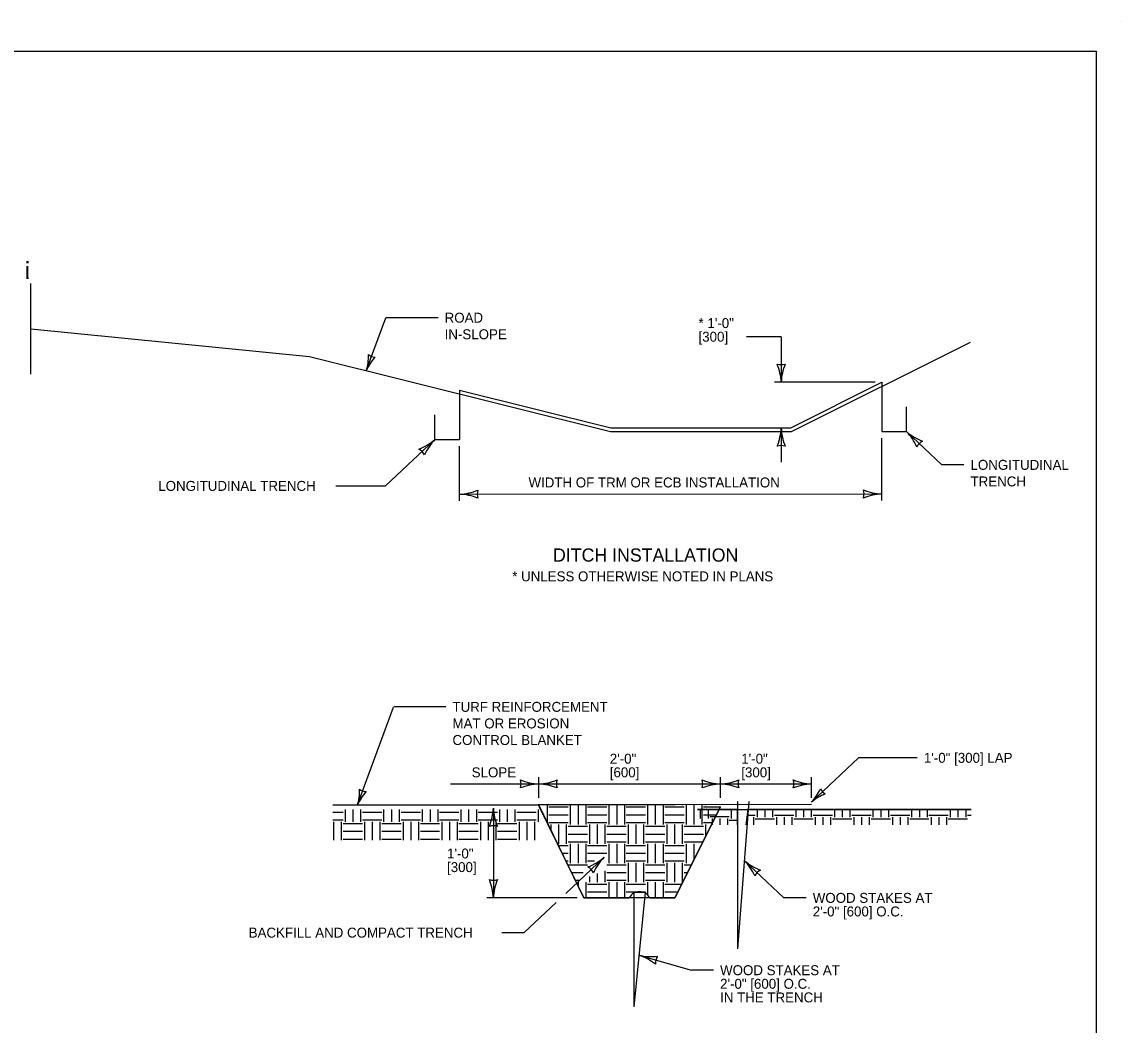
# Model space of a CAD drawing. Extents: x 49977.1 to 50021, y 49987.6 to 50011.4.
# Drawn here: x 50010.27 to 50016.9, y 49993.13 to 49999.18 of the extents above; entities that cross this region are included whole.
import ezdxf

# ---------------------------------------------------------------- set-up
doc = ezdxf.new("R2010")
doc.units = 0
for name, color, linetype in [('Level 1', 7, 'Continuous'), ('Level 2', 7, 'Continuous'), ('Level 3', 7, 'Continuous'), ('Level 5', 7, 'Continuous'), ('Level 60', 7, 'Continuous')]:
    doc.layers.add(name, color=color, linetype=linetype)

msp = doc.modelspace()

# ---------------------------------------------------------------- linework, layer by layer
at = {"layer": 'Level 1'}
for p, q in [((50016.9001, 49999.1756), (50016.9001, 49999.1756)), ((50010.3258, 49997.3257), (50012.0064, 49997.158)), ((50014.9133, 49996.7055), (50015.9917, 49997.2455)), ((50012.0064, 49997.158), (50013.8211, 49996.7055)), ((50014.9082, 49996.7274), (50015.4574, 49997.0024)), ((50015.4574, 49997.0024), (50015.4574, 49996.7055)), ((50012.9111, 49996.9549), (50013.8237, 49996.7274)), ((50012.9111, 49996.9549), (50012.9111, 49996.658)), ((50012.7626, 49996.658), (50012.7626, 49996.8065)), ((50015.6059, 49996.7055), (50015.6059, 49996.854)), ((50013.8237, 49996.7274), (50014.9082, 49996.7274)), ((50012.7626, 49996.658), (50012.9111, 49996.658)), ((50013.8211, 49996.7055), (50014.9133, 49996.7055)), ((50015.4574, 49996.7055), (50015.6059, 49996.7055)), ((50014.6556, 49994.474), (50014.5869, 49993.5859)), ((50014.5869, 49994.474), (50014.5869, 49993.5859)), ((50012.1463, 49994.4539), (50013.3822, 49994.4539)), ((50012.1463, 49994.4105), (50012.2084, 49994.4105)), ((50012.2201, 49994.4257), (50012.2201, 49994.3523)), ((50012.2667, 49994.4257), (50012.2667, 49994.3523)), ((50012.3133, 49994.4257), (50012.3133, 49994.3523)), ((50012.3249, 49994.4105), (50012.4414, 49994.4105)), ((50012.4531, 49994.4257), (50012.4531, 49994.3523)), ((50012.4997, 49994.4257), (50012.4997, 49994.3523)), ((50012.5463, 49994.4257), (50012.5463, 49994.3523)), ((50012.5579, 49994.4105), (50012.6744, 49994.4105)), ((50012.6861, 49994.4257), (50012.6861, 49994.3523)), ((50012.7327, 49994.4257), (50012.7327, 49994.3523)), ((50012.7792, 49994.4257), (50012.7792, 49994.3523)), ((50012.7909, 49994.4105), (50012.9074, 49994.4105)), ((50012.919, 49994.4257), (50012.919, 49994.3523)), ((50012.9656, 49994.4257), (50012.9656, 49994.3523)), ((50013.0122, 49994.4257), (50013.0122, 49994.3523)), ((50013.0239, 49994.4105), (50013.1404, 49994.4105)), ((50013.152, 49994.4257), (50013.152, 49994.3523)), ((50013.1986, 49994.4257), (50013.1986, 49994.3523)), ((50013.2452, 49994.4257), (50013.2452, 49994.3523)), ((50013.2569, 49994.4105), (50013.3734, 49994.4105)), ((50013.385, 49994.4257), (50013.385, 49994.3523)), ((50013.4391, 49994.4522), (50013.4391, 49994.3437)), ((50013.4499, 49994.4414), (50013.5664, 49994.4414)), ((50013.4615, 49994.4541), (50013.4615, 49994.4522)), ((50013.5081, 49994.4542), (50013.5081, 49994.4522)), ((50013.5547, 49994.4543), (50013.5547, 49994.4522)), ((50013.5789, 49994.4522), (50013.5789, 49994.3357)), ((50013.6255, 49994.4522), (50013.6255, 49994.3357)), ((50013.6721, 49994.4522), (50013.6721, 49994.3357)), ((50013.6829, 49994.4414), (50013.7994, 49994.4414)), ((50013.6945, 49994.4547), (50013.6945, 49994.4522)), ((50013.7411, 49994.4548), (50013.7411, 49994.4522)), ((50013.7877, 49994.4549), (50013.7877, 49994.4522)), ((50013.8119, 49994.4522), (50013.8119, 49994.3357)), ((50013.8585, 49994.4522), (50013.8585, 49994.3357)), ((50013.9051, 49994.4522), (50013.9051, 49994.3357)), ((50013.9159, 49994.4414), (50014.0324, 49994.4414)), ((50013.9275, 49994.4553), (50013.9275, 49994.4522)), ((50013.9741, 49994.4554), (50013.9741, 49994.4522)), ((50014.0207, 49994.4556), (50014.0207, 49994.4522)), ((50014.0449, 49994.4522), (50014.0449, 49994.3357)), ((50014.0915, 49994.4522), (50014.0915, 49994.3357)), ((50014.1381, 49994.4522), (50014.1381, 49994.3357)), ((50014.1488, 49994.4414), (50014.2653, 49994.4414)), ((50014.1605, 49994.4559), (50014.1605, 49994.4522)), ((50014.2071, 49994.456), (50014.2071, 49994.4522)), ((50014.2537, 49994.4562), (50014.2537, 49994.4522)), ((50014.2779, 49994.4522), (50014.2779, 49994.3357)), ((50014.3245, 49994.4522), (50014.3245, 49994.3357)), ((50014.3463, 49994.4257), (50015.9963, 49994.4257)), ((50014.5869, 49994.4257), (50014.3463, 49994.4257)), ((50014.3627, 49994.4257), (50014.3627, 49994.3726)), ((50014.3711, 49994.4522), (50014.3711, 49994.3357)), ((50014.3818, 49994.4414), (50014.4842, 49994.4414)), ((50014.3935, 49994.4565), (50014.3935, 49994.4522)), ((50014.4093, 49994.4257), (50014.4093, 49994.3726)), ((50014.5491, 49994.4257), (50014.5491, 49994.3726)), ((50014.5869, 49994.334), (50014.5869, 49994.4257)), ((50014.6496, 49994.4257), (50014.6381, 49994.334)), ((50015.9963, 49994.4257), (50014.6496, 49994.4257)), ((50014.7052, 49994.4257), (50014.7052, 49994.3799)), ((50014.7518, 49994.4257), (50014.7518, 49994.3799)), ((50014.7984, 49994.4257), (50014.7984, 49994.3799)), ((50014.9382, 49994.4257), (50014.9382, 49994.3799)), ((50014.9848, 49994.4257), (50014.9848, 49994.3799)), ((50015.0314, 49994.4257), (50015.0314, 49994.3799)), ((50015.1712, 49994.4257), (50015.1712, 49994.3799)), ((50015.2178, 49994.4257), (50015.2178, 49994.3799)), ((50015.2644, 49994.4257), (50015.2644, 49994.3799)), ((50015.4042, 49994.4257), (50015.4042, 49994.3799)), ((50015.4508, 49994.4257), (50015.4508, 49994.3799)), ((50015.4974, 49994.4257), (50015.4974, 49994.3799)), ((50015.6372, 49994.4257), (50015.6372, 49994.3799)), ((50015.6838, 49994.4257), (50015.6838, 49994.3799)), ((50015.7304, 49994.4257), (50015.7304, 49994.3799)), ((50015.8702, 49994.4257), (50015.8702, 49994.3799)), ((50015.9168, 49994.4257), (50015.9168, 49994.3799)), ((50015.9634, 49994.4257), (50015.9634, 49994.3799)), ((50012.1463, 49994.3639), (50012.2084, 49994.3639)), ((50012.151, 49994.3523), (50012.151, 49994.2423)), ((50012.1976, 49994.3523), (50012.1976, 49994.2423)), ((50012.2084, 49994.3415), (50012.3249, 49994.3415)), ((50012.3249, 49994.3639), (50012.4414, 49994.3639)), ((50012.3374, 49994.3523), (50012.3374, 49994.2423)), ((50012.384, 49994.3523), (50012.384, 49994.2423)), ((50012.4306, 49994.3523), (50012.4306, 49994.2423)), ((50012.4414, 49994.3415), (50012.5579, 49994.3415)), ((50012.5579, 49994.3639), (50012.6744, 49994.3639)), ((50012.5704, 49994.3523), (50012.5704, 49994.2423)), ((50012.617, 49994.3523), (50012.617, 49994.2423)), ((50012.6636, 49994.3523), (50012.6636, 49994.2423)), ((50012.6744, 49994.3415), (50012.7909, 49994.3415)), ((50012.7909, 49994.3639), (50012.9074, 49994.3639)), ((50012.8034, 49994.3523), (50012.8034, 49994.2423)), ((50012.85, 49994.3523), (50012.85, 49994.2423)), ((50012.8966, 49994.3523), (50012.8966, 49994.2423)), ((50012.9074, 49994.3415), (50013.0239, 49994.3415)), ((50013.0239, 49994.3639), (50013.1404, 49994.3639)), ((50013.0364, 49994.3523), (50013.0364, 49994.2423)), ((50013.083, 49994.3523), (50013.083, 49994.2423)), ((50013.1296, 49994.3523), (50013.1296, 49994.2423)), ((50013.1404, 49994.3415), (50013.2569, 49994.3415)), ((50013.2569, 49994.3639), (50013.3734, 49994.3639)), ((50013.2694, 49994.3523), (50013.2694, 49994.2423)), ((50013.316, 49994.3523), (50013.316, 49994.2423)), ((50013.3626, 49994.3523), (50013.3626, 49994.2423)), ((50013.4499, 49994.3948), (50013.5664, 49994.3948)), ((50013.4499, 49994.3482), (50013.5664, 49994.3482)), ((50013.6829, 49994.3948), (50013.7994, 49994.3948)), ((50013.6829, 49994.3482), (50013.7994, 49994.3482)), ((50013.9159, 49994.3948), (50014.0324, 49994.3948)), ((50013.9159, 49994.3482), (50014.0324, 49994.3482)), ((50014.1488, 49994.3948), (50014.2653, 49994.3948)), ((50014.1488, 49994.3482), (50014.2653, 49994.3482)), ((50014.3818, 49994.3948), (50014.4609, 49994.3948)), ((50014.3818, 49994.3482), (50014.4376, 49994.3482)), ((50014.4209, 49994.3842), (50014.5374, 49994.3842)), ((50014.4334, 49994.3726), (50014.4334, 49994.334)), ((50014.48, 49994.3726), (50014.48, 49994.334)), ((50014.5266, 49994.3726), (50014.5266, 49994.334)), ((50014.5374, 49994.3618), (50014.5869, 49994.3618)), ((50014.6453, 49994.3916), (50014.6936, 49994.3916)), ((50014.6828, 49994.3799), (50014.6828, 49994.334)), ((50014.6936, 49994.3691), (50014.8101, 49994.3691)), ((50014.8101, 49994.3916), (50014.9266, 49994.3916)), ((50014.8226, 49994.3799), (50014.8226, 49994.334)), ((50014.8692, 49994.3799), (50014.8692, 49994.334)), ((50014.9158, 49994.3799), (50014.9158, 49994.334)), ((50014.9266, 49994.3691), (50015.0431, 49994.3691)), ((50015.0431, 49994.3916), (50015.1596, 49994.3916)), ((50015.0556, 49994.3799), (50015.0556, 49994.334)), ((50015.1022, 49994.3799), (50015.1022, 49994.334)), ((50015.1488, 49994.3799), (50015.1488, 49994.334)), ((50015.1596, 49994.3691), (50015.2761, 49994.3691)), ((50015.2761, 49994.3916), (50015.3926, 49994.3916)), ((50015.2886, 49994.3799), (50015.2886, 49994.334)), ((50015.3352, 49994.3799), (50015.3352, 49994.334)), ((50015.3818, 49994.3799), (50015.3818, 49994.334)), ((50015.3926, 49994.3691), (50015.509, 49994.3691)), ((50015.509, 49994.3916), (50015.6255, 49994.3916)), ((50015.5216, 49994.3799), (50015.5216, 49994.334)), ((50015.5682, 49994.3799), (50015.5682, 49994.334)), ((50015.6148, 49994.3799), (50015.6148, 49994.334)), ((50015.6255, 49994.3691), (50015.742, 49994.3691)), ((50015.742, 49994.3916), (50015.8585, 49994.3916)), ((50015.7546, 49994.3799), (50015.7546, 49994.334)), ((50015.8012, 49994.3799), (50015.8012, 49994.334)), ((50015.8478, 49994.3799), (50015.8478, 49994.334)), ((50015.8585, 49994.3691), (50015.975, 49994.3691)), ((50015.975, 49994.3916), (50015.9963, 49994.3916)), ((50012.2084, 49994.2949), (50012.3249, 49994.2949)), ((50012.4414, 49994.2949), (50012.5579, 49994.2949)), ((50012.6744, 49994.2949), (50012.7909, 49994.2949)), ((50012.9074, 49994.2949), (50013.0239, 49994.2949)), ((50013.1404, 49994.2949), (50013.2569, 49994.2949)), ((50013.4483, 49994.3249), (50013.4499, 49994.3249)), ((50013.4615, 49994.3365), (50013.4615, 49994.298)), ((50013.5081, 49994.3365), (50013.5081, 49994.22)), ((50013.5547, 49994.3365), (50013.5547, 49994.22)), ((50013.5664, 49994.3249), (50013.6829, 49994.3249)), ((50013.5664, 49994.2783), (50013.6829, 49994.2783)), ((50013.6945, 49994.3365), (50013.6945, 49994.22)), ((50013.7411, 49994.3365), (50013.7411, 49994.22)), ((50013.7877, 49994.3365), (50013.7877, 49994.22)), ((50013.7994, 49994.3249), (50013.9159, 49994.3249)), ((50013.7994, 49994.2783), (50013.9159, 49994.2783)), ((50013.9275, 49994.3365), (50013.9275, 49994.22)), ((50013.9741, 49994.3365), (50013.9741, 49994.22)), ((50014.0207, 49994.3365), (50014.0207, 49994.22)), ((50014.0324, 49994.3249), (50014.1488, 49994.3249)), ((50014.0324, 49994.2783), (50014.1488, 49994.2783)), ((50014.1605, 49994.3365), (50014.1605, 49994.22)), ((50014.2071, 49994.3365), (50014.2071, 49994.22)), ((50014.2537, 49994.3365), (50014.2537, 49994.22)), ((50014.2653, 49994.3249), (50014.3818, 49994.3249)), ((50014.2653, 49994.2783), (50014.3818, 49994.2783)), ((50014.3935, 49994.3365), (50014.3935, 49994.26)), ((50012.2084, 49994.2483), (50012.3249, 49994.2483)), ((50012.4414, 49994.2483), (50012.5579, 49994.2483)), ((50012.6744, 49994.2483), (50012.7909, 49994.2483)), ((50012.9074, 49994.2483), (50013.0239, 49994.2483)), ((50013.1404, 49994.2483), (50013.2569, 49994.2483)), ((50013.5051, 49994.2092), (50013.5664, 49994.2092)), ((50013.5664, 49994.2317), (50013.6829, 49994.2317)), ((50013.5789, 49994.22), (50013.5789, 49994.1035)), ((50013.6255, 49994.22), (50013.6255, 49994.1035)), ((50013.6721, 49994.22), (50013.6721, 49994.1035)), ((50013.6829, 49994.2092), (50013.7994, 49994.2092)), ((50013.7994, 49994.2317), (50013.9159, 49994.2317)), ((50013.8119, 49994.22), (50013.8119, 49994.1035)), ((50013.8585, 49994.22), (50013.8585, 49994.1035)), ((50013.9051, 49994.22), (50013.9051, 49994.1035)), ((50013.9159, 49994.2092), (50014.0324, 49994.2092)), ((50014.0324, 49994.2317), (50014.1488, 49994.2317)), ((50014.0449, 49994.22), (50014.0449, 49994.1035)), ((50014.0915, 49994.22), (50014.0915, 49994.1035)), ((50014.1381, 49994.22), (50014.1381, 49994.1035)), ((50014.1488, 49994.2092), (50014.2653, 49994.2092)), ((50014.2653, 49994.2317), (50014.3793, 49994.2317)), ((50014.2779, 49994.22), (50014.2779, 49994.1035)), ((50014.3245, 49994.22), (50014.3245, 49994.1219)), ((50014.3711, 49994.22), (50014.3711, 49994.2151)), ((50013.528, 49994.1626), (50013.5664, 49994.1626)), ((50013.6829, 49994.1626), (50013.7994, 49994.1626)), ((50013.9159, 49994.1626), (50014.0324, 49994.1626)), ((50014.1488, 49994.1626), (50014.2653, 49994.1626)), ((50013.5508, 49994.116), (50013.5664, 49994.116)), ((50013.5664, 49994.0927), (50013.6829, 49994.0927)), ((50013.6829, 49994.116), (50013.7244, 49994.116)), ((50013.7994, 49994.0927), (50013.9159, 49994.0927)), ((50013.9159, 49994.116), (50014.0324, 49994.116)), ((50013.9275, 49994.1044), (50013.9275, 49993.9879)), ((50013.9741, 49994.1044), (50013.9741, 49993.9879)), ((50014.0207, 49994.1044), (50014.0207, 49993.9879)), ((50014.0324, 49994.0927), (50014.1488, 49994.0927)), ((50014.1488, 49994.116), (50014.2653, 49994.116)), ((50014.1605, 49994.1044), (50014.1605, 49993.9879)), ((50014.2071, 49994.1044), (50014.2071, 49993.9879)), ((50014.2537, 49994.1044), (50014.2537, 49993.9879)), ((50014.2653, 49994.0927), (50014.3098, 49994.0927)), ((50013.5851, 49994.0461), (50013.6562, 49994.0461)), ((50013.6945, 49994.0225), (50013.6945, 49993.9879)), ((50013.7411, 49994.0405), (50013.7411, 49993.9879)), ((50013.7877, 49994.0573), (50013.7877, 49993.9879)), ((50013.7994, 49994.0461), (50013.9159, 49994.0461)), ((50014.0324, 49994.0461), (50014.1488, 49994.0461)), ((50014.2653, 49994.0461), (50014.2866, 49994.0461)), ((50013.608, 49993.9995), (50013.6343, 49993.9995)), ((50013.6255, 49993.9879), (50013.6255, 49993.9639)), ((50013.6721, 49993.9879), (50013.6721, 49993.8933)), ((50013.6829, 49993.977), (50013.7994, 49993.977)), ((50013.7994, 49993.9995), (50013.9159, 49993.9995)), ((50013.8119, 49993.9879), (50013.8119, 49993.8933)), ((50013.8585, 49993.9879), (50013.8585, 49993.8933)), ((50013.9051, 49993.9879), (50013.9051, 49993.8933)), ((50013.9159, 49993.977), (50014.0324, 49993.977)), ((50014.0324, 49993.9995), (50014.1488, 49993.9995)), ((50014.0449, 49993.9879), (50014.0449, 49993.9109)), ((50014.0915, 49993.9879), (50014.0915, 49993.8933)), ((50014.1381, 49993.9879), (50014.1381, 49993.8933)), ((50014.1488, 49993.977), (50014.252, 49993.977)), ((50013.6829, 49993.9304), (50013.7994, 49993.9304)), ((50013.9159, 49993.9304), (50013.9863, 49993.9304)), ((50013.9615, 49993.9285), (50013.9615, 49993.2356)), ((50014.0303, 49993.9285), (50013.9615, 49993.2356)), ((50013.9615, 49993.9285), (50014.0303, 49993.9285)), ((50014.0056, 49993.9304), (50014.0324, 49993.9304)), ((50014.1488, 49993.9304), (50014.2287, 49993.9304))]:
    msp.add_line(p, q, dxfattribs=at)
msp.add_lwpolyline([(49999.3835, 49998.9992), (50016.7501, 49998.9992), (50016.7501, 49987.7988), (49999.3835, 49987.7988)], close=True, dxfattribs=at)
for points in [[(50014.4996, 49994.4568), (50013.385, 49994.4539)], [(50013.385, 49994.4539), (50013.3902, 49994.4433), (50013.6601, 49993.8933), (50013.9341, 49993.8933)], [(50014.0578, 49993.8933), (50014.2101, 49993.8933), (50014.4393, 49994.3516), (50014.4851, 49994.4433)]]:
    msp.add_lwpolyline(points, dxfattribs=at)
msp.add_arc((50013.9959, 49993.8616), 0.0695, 27.10314, 152.89686, dxfattribs=at)
at = {"layer": 'Level 3'}
for p, q in [((50012.3482, 49997.0727), (50012.4662, 49997.3913)), ((50012.7809, 49997.3923), (50012.4665, 49997.3923)), ((50014.8506, 49997.2775), (50014.6413, 49997.2775)), ((50014.8506, 49997.2775), (50014.8506, 49997.0024)), ((50015.4174, 49997.0024), (50014.8106, 49997.0024)), ((50014.8506, 49996.7274), (50014.8506, 49996.5209)), ((50012.7626, 49996.658), (50012.4652, 49996.3778)), ((50015.4574, 49996.2892), (50015.4574, 49996.6655)), ((50015.6059, 49996.7055), (50015.8191, 49996.5047)), ((50012.9111, 49996.2878), (50012.9111, 49996.618)), ((50015.9525, 49996.5047), (50015.8191, 49996.5047)), ((50012.1647, 49996.3778), (50012.4652, 49996.3778)), ((50012.9111, 49996.3278), (50015.4574, 49996.3292)), ((50012.2948, 49994.4539), (50012.5134, 49995.0443)), ((50012.8282, 49995.0453), (50012.5138, 49995.0453)), ((50015.0342, 49994.4715), (50015.317, 49994.7379)), ((50015.6714, 49994.7379), (50015.317, 49994.7379)), ((50013.3887, 49994.4968), (50013.3887, 49994.6204)), ((50014.4842, 49994.4968), (50014.4842, 49994.6204)), ((50015.0342, 49994.4968), (50015.0342, 49994.6204)), ((50012.8572, 49994.5804), (50013.3887, 49994.5804)), ((50013.3887, 49994.5804), (50014.4842, 49994.5804)), ((50014.4842, 49994.5804), (50015.0342, 49994.5804)), ((50013.1149, 49994.4349), (50013.1149, 49993.8933)), ((50013.7824, 49994.1381), (50013.5517, 49993.9207)), ((50014.6281, 49994.1189), (50014.8675, 49993.8933)), ((50013.6201, 49993.8933), (50013.0749, 49993.8933)), ((50015.001, 49993.8933), (50014.8675, 49993.8933)), ((50013.4935, 49993.8658), (50013.3001, 49993.6837)), ((50013.1667, 49993.6837), (50013.3001, 49993.6837)), ((50013.9925, 49993.5478), (50014.3087, 49993.4571)), ((50014.4421, 49993.4571), (50014.3087, 49993.4571))]:
    msp.add_line(p, q, dxfattribs=at)
for centre, radius, start, end in [((50012.0828, 49997.1588), 0.279, 342.04462, 2.22813), ((50012.6171, 49996.9578), 0.2924, 137.60698, 156.85683), ((50012.4041, 49997.2236), 0.0687, 231.82296, 267.54532), ((50014.8506, 49997.1884), 0.0794, 252.13882, 287.86118), ((50014.5131, 49996.9857), 0.3379, 2.82731, 22.07716), ((50015.1728, 49996.9891), 0.3224, 157.45601, 177.63952), ((50014.5285, 49996.7406), 0.3224, 337.45601, 357.63952), ((50015.1881, 49996.744), 0.3379, 182.82731, 202.07716), ((50012.5433, 49996.9151), 0.3379, 291.21884, 310.46869), ((50012.9932, 49996.4327), 0.3224, 135.65648, 155.83999), ((50015.3753, 49996.4802), 0.3224, 24.16001, 44.34352), ((50015.8252, 49996.9626), 0.3379, 229.53131, 248.78116), ((50012.6273, 49996.5305), 0.0794, 25.43482, 61.15718), ((50014.8506, 49996.5414), 0.0794, 72.13882, 107.86118), ((50015.7412, 49996.578), 0.0794, 118.84282, 154.56518), ((50012.8944, 49996.6653), 0.3379, 272.82731, 292.07716), ((50012.8978, 49996.0057), 0.3224, 67.45601, 87.63952), ((50013.097, 49996.3278), 0.0794, 162.13882, 197.86118), ((50015.4707, 49996.6514), 0.3224, 247.45601, 267.63952), ((50015.2715, 49996.3292), 0.0794, 342.13882, 17.86118), ((50015.4741, 49995.9917), 0.3379, 92.82731, 112.07716), ((50013.402, 49994.9025), 0.3224, 247.45601, 267.63952), ((50013.2027, 49994.5804), 0.0794, 342.13882, 17.86118), ((50013.372, 49994.9179), 0.3379, 272.82731, 292.07716), ((50013.5746, 49994.5804), 0.0794, 162.13882, 197.86118), ((50014.4975, 49994.9025), 0.3224, 247.45601, 267.63952), ((50014.2982, 49994.5804), 0.0794, 342.13882, 17.86118), ((50014.4675, 49994.9179), 0.3379, 272.82731, 292.07716), ((50014.6701, 49994.5804), 0.0794, 162.13882, 197.86118), ((50015.0475, 49994.9025), 0.3224, 247.45601, 267.63952), ((50014.8482, 49994.5804), 0.0794, 342.13882, 17.86118), ((50012.0287, 49994.5376), 0.279, 342.04462, 2.22813), ((50012.35, 49994.6025), 0.0687, 231.82296, 267.54532), ((50013.4054, 49994.2429), 0.3379, 92.82731, 112.07716), ((50013.3754, 49994.2582), 0.3224, 67.45601, 87.63952), ((50014.5009, 49994.2429), 0.3379, 92.82731, 112.07716), ((50014.4709, 49994.2582), 0.3224, 67.45601, 87.63952), ((50015.0509, 49994.2429), 0.3379, 92.82731, 112.07716), ((50014.833, 49994.6648), 0.279, 315.65648, 335.83999), ((50015.1496, 49994.5801), 0.0687, 205.43482, 241.15718), ((50012.563, 49994.3367), 0.2924, 137.60698, 156.85683), ((50015.2223, 49994.2473), 0.2924, 111.21884, 130.46869), ((50012.7927, 49994.4482), 0.3224, 337.45601, 357.63952), ((50013.4524, 49994.4516), 0.3379, 182.82731, 202.07716), ((50013.1149, 49994.249), 0.0794, 72.13882, 107.86118), ((50013.5631, 49994.3951), 0.3379, 291.21884, 310.46869), ((50014.013, 49993.9127), 0.3224, 135.65648, 155.83999), ((50013.647, 49994.0105), 0.0794, 25.43482, 61.15718), ((50014.3975, 49993.8935), 0.3224, 24.16001, 44.34352), ((50014.8475, 49994.376), 0.3379, 229.53131, 248.78116), ((50014.7635, 49993.9914), 0.0794, 118.84282, 154.56518), ((50013.1149, 49994.0792), 0.0794, 252.13882, 287.86118), ((50012.7774, 49993.8766), 0.3379, 2.82731, 22.07716), ((50013.437, 49993.88), 0.3224, 157.45601, 177.63952), ((50013.8909, 49993.2417), 0.3224, 51.45141, 71.63492), ((50014.0695, 49993.8768), 0.3379, 256.82271, 276.07256), ((50014.1712, 49993.4965), 0.0794, 146.13422, 181.85658)]:
    msp.add_arc(centre, radius, start, end, dxfattribs=at)
at = {"layer": 'Level 5'}
msp.add_line((50010.3258, 49997.0526), (50010.3258, 49997.5988), dxfattribs=at)
at = {"layer": 'Level 60'}
for points in [[(50013.3887, 49994.4539), (50015.0343, 49994.4582)], [(50014.4851, 49994.4433), (50014.2101, 49993.8933), (50013.6601, 49993.8933), (50013.3887, 49994.4539)]]:
    msp.add_lwpolyline(points, dxfattribs=at)

# ---------------------------------------------------------------- texts
at = {"layer": 'Level 2'}
for s, height, p in [('¡', 0.1092, (50010.2802, 49997.6509)), ('ROAD', 0.06, (50012.8209, 49997.3623)), ('* 1\'-0" ', 0.06, (50014.3521, 49997.3295)), ('IN-SLOPE', 0.06, (50012.8209, 49997.2623)), ('[300] ', 0.06, (50014.3521, 49997.2475)), ('LONGITUDINAL ', 0.06, (50015.9925, 49996.4747)), ('LONGITUDINAL TRENCH', 0.06, (50011.0939, 49996.3478)), ('WIDTH OF TRM OR ECB INSTALLATION', 0.06, (50013.3267, 49996.3685)), ('TRENCH', 0.06, (50015.9925, 49996.3747)), ('DITCH INSTALLATION', 0.08, (50013.4745, 49995.9209)), ('* UNLESS OTHERWISE NOTED IN PLANS', 0.06, (50013.2286, 49995.8024)), ('TURF REINFORCEMENT ', 0.06, (50012.8682, 49995.0153)), ('MAT OR EROSION ', 0.06, (50012.8682, 49994.9153)), ('CONTROL BLANKET', 0.06, (50012.8682, 49994.8153)), ('2\'-0" ', 0.06, (50013.8168, 49994.7024)), ('1\'-0" ', 0.06, (50014.61, 49994.7024)), ('1\'-0" [300] LAP', 0.06, (50015.7114, 49994.7079)), ('SLOPE', 0.06, (50012.9842, 49994.6204)), ('[600]', 0.06, (50013.8168, 49994.6204)), ('[300]', 0.06, (50014.61, 49994.6204)), ('1\'-0" ', 0.06, (50012.8354, 49994.1308)), ('[300]', 0.06, (50012.8354, 49994.0488)), ('WOOD STAKES AT', 0.06, (50015.041, 49993.8633)), ('2\'-0" [600] O.C.', 0.06, (50015.041, 49993.7813)), ('BACKFILL AND COMPACT TRENCH', 0.06, (50011.6392, 49993.6537)), ('WOOD STAKES AT', 0.06, (50014.4821, 49993.4271)), ('2\'-0" [600] O.C.', 0.06, (50014.4821, 49993.3451)), ('IN THE TRENCH', 0.06, (50014.4821, 49993.2631))]:
    msp.add_text(s, height=height, dxfattribs=at).set_placement(p)

doc.saveas('drawing.dxf')
